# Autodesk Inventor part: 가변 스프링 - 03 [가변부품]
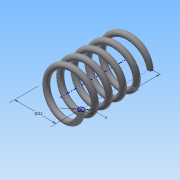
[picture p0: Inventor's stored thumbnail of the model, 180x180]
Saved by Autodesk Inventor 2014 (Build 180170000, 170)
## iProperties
Created: 2015-09
Part Number: 가변 스프링 - 03 [가변부품]
Material: 강철, 탄소
Document SubType Name: Modeling
Designer: study
Density: 1 g/cm^3
Appearance: 반연마
Author: study
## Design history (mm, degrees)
sketch "스케치1"
  geometry: L1 (0, 0)-(11, 0); L2 (11, 0)-(11, 40.245); L3 (11, 40.245)-(0, 40.245); L4 (0, 40.245)-(0, 0); C1 r 1.5 at (11, 0)
  constraints: 8 end point, 2 parallel, 1 centre point, 1 coincident, 1 horizontal, 1 perpendicular
  dimensions: "d0" = 22 diameter of L2 L4; "d1" = 40.2455 distance between parallel lines of L3 L1 (derived); "d2" = 3 diameter of C1
feature "코일1" sketch "스케치1" pitch "d3" = 10; turns "d5" = 5; dims "d4" = 40.2455 (= d1), "d6" = 0, angle "d7" = 90 deg, angle "d8" = 90 deg, "d9" = 0, "d10" = 0
node "작업 평면1"
sketch "스케치2"
  geometry: L1 (-12.5, 0)-(-9.5, 0) reference; L2 (-12.5, 0)-(-9.5, 0) reference; 1 further point
  constraints: 2 horizontal alignment
extrude "돌출1" cut sketch "스케치2" stored distance "d12" = 10; taper "d13" = 0 deg
node "작업 평면2"
sketch "스케치3"
  geometry: L1 (-9.5, 0)-(-12.5, 0) reference; 1 further point
  constraints: 1 horizontal alignment
extrude "돌출2" cut sketch "스케치3" stored distance "d15" = 10; taper "d16" = 0 deg
node "솔리드1"
node "절단 모서리 투영1"
node "절단 모서리 투영2"
node "절단 모서리 투영3"
other parameters: "d11" = 0, "d14" = 40.2455 (= d1)
